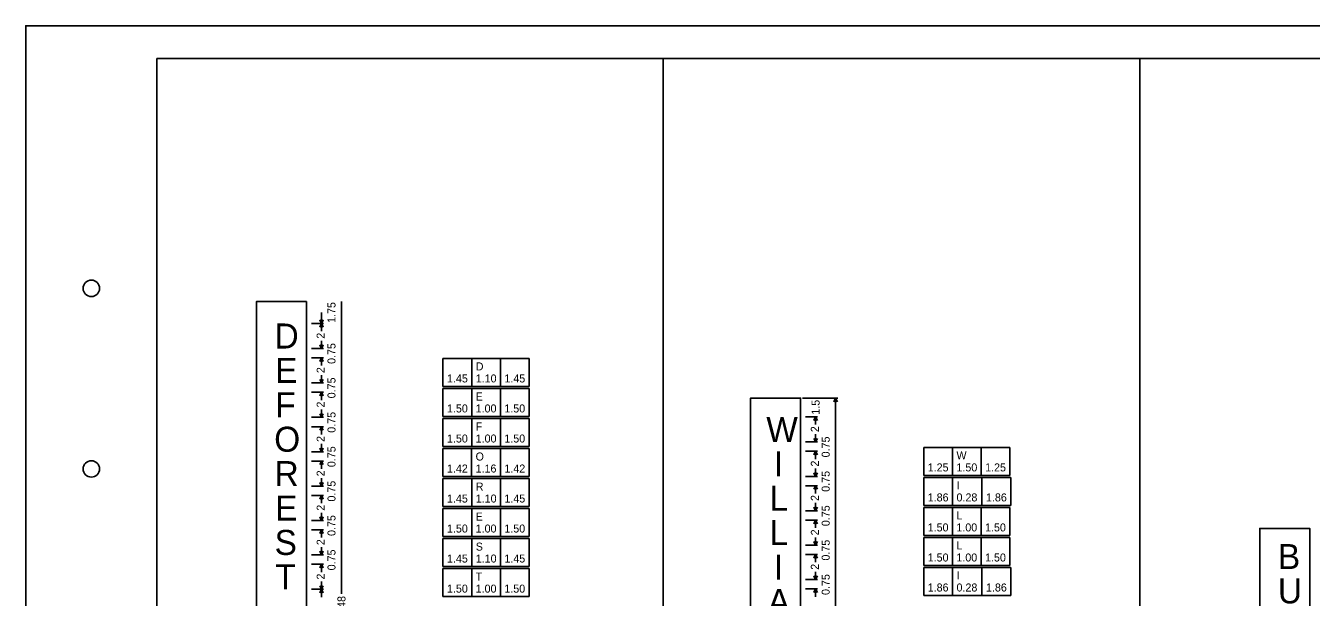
# Model space of a CAD drawing. Extents: x -16.4 to 26.5, y -12.9 to 9.1.
# Drawn here: x -16.37 to 3.22, y 0.39 to 9.09 of the extents above; entities that cross this region are included whole.
import ezdxf

# ---------------------------------------------------------------- set-up
doc = ezdxf.new("R2010")
doc.units = 0
for name, color, linetype in [('SH_Border', 7, 'Continuous'), ('SH_Cut_Line', 7, 'Continuous'), ('SH_Text', 7, 'Continuous')]:
    doc.layers.add(name, color=color, linetype=linetype)

msp = doc.modelspace()

# ---------------------------------------------------------------- linework, layer by layer
at = {"layer": 'SH_Border'}
msp.add_lwpolyline([(-14.371, 8.593), (17.129, 8.593), (17.129, -12.407), (-14.371, -12.407)], close=True, dxfattribs=at)
for centre in [(-15.371, 5.093), (-15.371, 2.343)]:
    msp.add_circle(centre, 0.125, dxfattribs=at)
at = {"layer": 'SH_Cut_Line'}
msp.add_lwpolyline([(-16.371, -12.907), (17.629, -12.907), (17.629, 9.093), (-16.371, 9.093)], close=True, dxfattribs=at)
at = {"layer": 'SH_Text'}
for p, q in [((-6.656, -12.407), (-6.656, 8.593)), ((0.606, -12.407), (0.606, 8.593)), ((-11.865, 4.724), (-11.865, 4.558)), ((-11.56, 0.443), (-11.56, 4.891)), ((-11.834, 4.558), (-12.017, 4.558)), ((-11.892, 4.612), (-11.865, 4.558)), ((-11.892, 4.503), (-11.865, 4.558)), ((-11.838, 4.612), (-11.865, 4.558)), ((-11.865, 4.439), (-11.865, 4.558)), ((-11.838, 4.503), (-11.865, 4.558)), ((-11.834, 4.177), (-12.017, 4.177)), ((-11.892, 4.231), (-11.865, 4.177)), ((-11.865, 4.295), (-11.865, 4.177)), ((-11.838, 4.231), (-11.865, 4.177)), ((-11.834, 4.034), (-12.017, 4.034)), ((-11.892, 3.979), (-11.865, 4.034)), ((-11.865, 3.916), (-11.865, 4.034)), ((-11.838, 3.979), (-11.865, 4.034)), ((-10.013, 4.026), (-10.013, 3.599)), ((-8.7, 4.026), (-10.013, 4.026)), ((-9.575, 4.026), (-9.575, 3.599)), ((-9.138, 4.026), (-9.138, 3.599)), ((-8.7, 4.026), (-8.7, 3.599)), ((-11.865, 3.771), (-11.865, 3.653)), ((-11.834, 3.653), (-12.017, 3.653)), ((-11.892, 3.707), (-11.865, 3.653)), ((-11.838, 3.707), (-11.865, 3.653)), ((-8.7, 3.599), (-10.013, 3.599)), ((-10.013, 3.568), (-10.013, 3.142)), ((-8.701, 3.568), (-10.013, 3.568)), ((-9.576, 3.568), (-9.576, 3.142)), ((-9.138, 3.568), (-9.138, 3.142)), ((-8.701, 3.568), (-8.701, 3.142)), ((-11.834, 3.51), (-12.017, 3.51)), ((-11.892, 3.456), (-11.865, 3.51)), ((-11.865, 3.392), (-11.865, 3.51)), ((-11.838, 3.456), (-11.865, 3.51)), ((-3.999, 3.421), (-4.533, 3.421)), ((-4.304, 3.421), (-4.487, 3.421)), ((-4.057, 3.366), (-4.03, 3.421)), ((-4.03, -0.457), (-4.03, 3.421)), ((-4.002, 3.366), (-4.03, 3.421)), ((-11.892, 3.183), (-11.865, 3.129)), ((-11.865, 3.247), (-11.865, 3.129)), ((-11.838, 3.183), (-11.865, 3.129)), ((-8.701, 3.142), (-10.013, 3.142)), ((-4.304, 3.135), (-4.487, 3.135)), ((-4.362, 3.08), (-4.335, 3.135)), ((-4.335, 3.017), (-4.335, 3.135)), ((-4.307, 3.08), (-4.335, 3.135)), ((-11.834, 3.129), (-12.017, 3.129)), ((-11.834, 2.986), (-12.017, 2.986)), ((-11.892, 2.932), (-11.865, 2.986)), ((-11.865, 2.868), (-11.865, 2.986)), ((-11.838, 2.932), (-11.865, 2.986)), ((-10.013, 3.111), (-10.013, 2.684)), ((-8.701, 3.111), (-10.013, 3.111)), ((-9.576, 3.111), (-9.576, 2.684)), ((-9.138, 3.111), (-9.138, 2.684)), ((-8.701, 3.111), (-8.701, 2.684)), ((-4.304, 2.754), (-4.487, 2.754)), ((-4.362, 2.808), (-4.335, 2.754)), ((-4.335, 2.872), (-4.335, 2.754)), ((-4.307, 2.808), (-4.335, 2.754)), ((-11.834, 2.605), (-12.017, 2.605)), ((-11.892, 2.66), (-11.865, 2.605)), ((-11.865, 2.723), (-11.865, 2.605)), ((-11.838, 2.66), (-11.865, 2.605)), ((-8.701, 2.684), (-10.013, 2.684)), ((-10.013, 2.654), (-10.013, 2.227)), ((-8.702, 2.654), (-10.013, 2.654)), ((-9.577, 2.654), (-9.577, 2.227)), ((-9.138, 2.654), (-9.138, 2.227)), ((-8.702, 2.654), (-8.702, 2.227)), ((-4.304, 2.611), (-4.487, 2.611)), ((-4.362, 2.557), (-4.335, 2.611)), ((-4.335, 2.493), (-4.335, 2.611)), ((-4.307, 2.557), (-4.335, 2.611)), ((-2.688, 2.671), (-2.688, 2.244)), ((-1.375, 2.671), (-2.688, 2.671)), ((-2.25, 2.671), (-2.25, 2.244)), ((-1.813, 2.671), (-1.813, 2.244)), ((-1.375, 2.671), (-1.375, 2.244)), ((-11.834, 2.462), (-12.017, 2.462)), ((-11.892, 2.408), (-11.865, 2.462)), ((-11.865, 2.344), (-11.865, 2.462)), ((-11.838, 2.408), (-11.865, 2.462)), ((-11.865, 2.2), (-11.865, 2.081)), ((-8.702, 2.227), (-10.013, 2.227)), ((-10.013, 2.197), (-10.013, 1.77)), ((-8.7, 2.197), (-10.013, 2.197)), ((-9.575, 2.197), (-9.575, 1.77)), ((-9.138, 2.197), (-9.138, 1.77)), ((-8.7, 2.197), (-8.7, 1.77)), ((-4.304, 2.23), (-4.487, 2.23)), ((-4.362, 2.285), (-4.335, 2.23)), ((-4.335, 2.348), (-4.335, 2.23)), ((-4.307, 2.285), (-4.335, 2.23)), ((-1.375, 2.244), (-2.688, 2.244)), ((-2.688, 2.214), (-2.688, 1.787)), ((-1.36, 2.214), (-2.688, 2.214)), ((-2.249, 2.214), (-2.249, 1.787)), ((-1.8, 2.214), (-1.8, 1.787)), ((-1.36, 2.214), (-1.36, 1.787)), ((-11.834, 2.081), (-12.017, 2.081)), ((-11.892, 2.136), (-11.865, 2.081)), ((-11.838, 2.136), (-11.865, 2.081)), ((-4.304, 2.087), (-4.487, 2.087)), ((-4.362, 2.033), (-4.335, 2.087)), ((-4.335, 1.969), (-4.335, 2.087)), ((-4.307, 2.033), (-4.335, 2.087)), ((-11.834, 1.938), (-12.017, 1.938)), ((-11.892, 1.884), (-11.865, 1.938)), ((-11.865, 1.82), (-11.865, 1.938)), ((-11.838, 1.884), (-11.865, 1.938)), ((-8.7, 1.77), (-10.013, 1.77)), ((-4.335, 1.824), (-4.335, 1.706)), ((-1.36, 1.787), (-2.688, 1.787)), ((-11.892, 1.612), (-11.865, 1.557)), ((-11.865, 1.676), (-11.865, 1.557)), ((-11.838, 1.612), (-11.865, 1.557)), ((-10.013, 1.74), (-10.013, 1.313)), ((-8.701, 1.74), (-10.013, 1.74)), ((-9.576, 1.74), (-9.576, 1.313)), ((-9.138, 1.74), (-9.138, 1.313)), ((-8.701, 1.74), (-8.701, 1.313)), ((-4.304, 1.706), (-4.487, 1.706)), ((-4.362, 1.761), (-4.335, 1.706)), ((-4.307, 1.761), (-4.335, 1.706)), ((-2.688, 1.756), (-2.688, 1.33)), ((-1.376, 1.756), (-2.688, 1.756)), ((-2.251, 1.756), (-2.251, 1.33)), ((-1.814, 1.756), (-1.814, 1.33)), ((-1.376, 1.756), (-1.376, 1.33)), ((-11.834, 1.557), (-12.017, 1.557)), ((-11.834, 1.414), (-12.017, 1.414)), ((-11.892, 1.36), (-11.865, 1.414)), ((-11.865, 1.296), (-11.865, 1.414)), ((-11.838, 1.36), (-11.865, 1.414)), ((-4.304, 1.563), (-4.487, 1.563)), ((-4.362, 1.509), (-4.335, 1.563)), ((-4.335, 1.445), (-4.335, 1.563)), ((-4.307, 1.509), (-4.335, 1.563)), ((-8.701, 1.313), (-10.013, 1.313)), ((-10.013, 1.282), (-10.013, 0.856)), ((-8.7, 1.282), (-10.013, 1.282)), ((-9.575, 1.282), (-9.575, 0.856)), ((-9.138, 1.282), (-9.138, 0.856)), ((-8.7, 1.282), (-8.7, 0.856)), ((-4.304, 1.182), (-4.487, 1.182)), ((-4.362, 1.237), (-4.335, 1.182)), ((-4.335, 1.301), (-4.335, 1.182)), ((-4.307, 1.237), (-4.335, 1.182)), ((-1.376, 1.33), (-2.688, 1.33)), ((-2.688, 1.299), (-2.688, 0.872)), ((-1.376, 1.299), (-2.688, 1.299)), ((-2.251, 1.299), (-2.251, 0.872)), ((-1.814, 1.299), (-1.814, 0.872)), ((-1.376, 1.299), (-1.376, 0.872)), ((-11.834, 1.033), (-12.017, 1.033)), ((-11.892, 1.088), (-11.865, 1.033)), ((-11.865, 1.152), (-11.865, 1.033)), ((-11.838, 1.088), (-11.865, 1.033)), ((-4.304, 1.039), (-4.487, 1.039)), ((-4.362, 0.985), (-4.335, 1.039)), ((-4.335, 0.921), (-4.335, 1.039)), ((-4.307, 0.985), (-4.335, 1.039)), ((-11.834, 0.891), (-12.017, 0.891)), ((-11.892, 0.836), (-11.865, 0.891)), ((-11.865, 0.772), (-11.865, 0.891)), ((-11.838, 0.836), (-11.865, 0.891)), ((-8.7, 0.856), (-10.013, 0.856)), ((-10.013, 0.825), (-10.013, 0.398)), ((-8.701, 0.825), (-10.013, 0.825)), ((-9.576, 0.825), (-9.576, 0.398)), ((-9.138, 0.825), (-9.138, 0.398)), ((-8.701, 0.825), (-8.701, 0.398)), ((-1.376, 0.872), (-2.688, 0.872)), ((-2.688, 0.842), (-2.688, 0.415)), ((-1.36, 0.842), (-2.688, 0.842)), ((-2.249, 0.842), (-2.249, 0.415)), ((-1.8, 0.842), (-1.8, 0.415)), ((-1.36, 0.842), (-1.36, 0.415)), ((-11.865, 0.628), (-11.865, 0.51)), ((-4.304, 0.658), (-4.487, 0.658)), ((-4.362, 0.713), (-4.335, 0.658)), ((-4.335, 0.777), (-4.335, 0.658)), ((-4.307, 0.713), (-4.335, 0.658)), ((-11.834, 0.51), (-12.017, 0.51)), ((-11.892, 0.564), (-11.865, 0.51)), ((-11.892, 0.455), (-11.865, 0.51)), ((-11.838, 0.564), (-11.865, 0.51)), ((-11.865, 0.391), (-11.865, 0.51)), ((-11.838, 0.455), (-11.865, 0.51)), ((-8.701, 0.398), (-10.013, 0.398)), ((-4.304, 0.516), (-4.487, 0.516)), ((-4.362, 0.461), (-4.335, 0.516)), ((-4.335, 0.397), (-4.335, 0.516)), ((-4.307, 0.461), (-4.335, 0.516)), ((-1.36, 0.415), (-2.688, 0.415))]:
    msp.add_line(p, q, dxfattribs=at)
for points in [[(-12.855, -4.253), (-12.093, -4.253), (-12.093, 4.891), (-12.855, 4.891), (-12.855, -4.253), (-12.855, -4.253)], [(-5.325, -4.58), (-4.563, -4.58), (-4.563, 3.421), (-5.325, 3.421), (-5.325, -4.58), (-5.325, -4.58)], [(2.432, -5.42), (3.194, -5.42), (3.194, 1.438), (2.432, 1.438), (2.432, -5.42), (2.432, -5.42)]]:
    msp.add_lwpolyline(points, dxfattribs=at)

# ---------------------------------------------------------------- texts
for s, height, p in [('1.75', 0.1219, (-11.651, 4.567)), ('2', 0.122, (-11.816, 4.326)), ('0.75', 0.1219, (-11.651, 3.942)), ('2', 0.122, (-11.816, 3.802)), ('0.75', 0.1219, (-11.651, 3.418)), ('2', 0.122, (-11.816, 3.278)), ('1.5', 0.1219, (-4.274, 3.169)), ('0.75', 0.1219, (-11.651, 2.894)), ('2', 0.122, (-4.286, 2.903)), ('2', 0.122, (-11.816, 2.754)), ('0.75', 0.1219, (-4.121, 2.519)), ('0.75', 0.1219, (-11.651, 2.37)), ('2', 0.122, (-4.286, 2.379)), ('2', 0.122, (-11.816, 2.23)), ('0.75', 0.1219, (-11.651, 1.846)), ('0.75', 0.1219, (-4.121, 1.995)), ('2', 0.122, (-11.816, 1.706)), ('2', 0.122, (-4.286, 1.855)), ('0.75', 0.1219, (-4.121, 1.471)), ('0.75', 0.1219, (-11.651, 1.322)), ('2', 0.122, (-4.286, 1.331)), ('2', 0.122, (-11.816, 1.182)), ('0.75', 0.1219, (-4.121, 0.947)), ('0.75', 0.1219, (-11.651, 0.798)), ('2', 0.122, (-4.286, 0.807)), ('2', 0.122, (-11.816, 0.658)), ('0.75', 0.1219, (-4.121, 0.423)), ('48', 0.1219, (-11.499, 0.226))]:
    msp.add_text(s, height=height, rotation=90.0002, dxfattribs=at).set_placement(p)
for s, height, p in [('D', 0.381, (-12.579, 4.177)), ('E', 0.381, (-12.57, 3.653)), ('D', 0.122, (-9.514, 3.843)), ('1.45', 0.1219, (-9.952, 3.66)), ('1.10', 0.1219, (-9.514, 3.66)), ('1.45', 0.1219, (-9.077, 3.66)), ('F', 0.381, (-12.57, 3.129)), ('E', 0.122, (-9.515, 3.385)), ('1.50', 0.1219, (-9.952, 3.203)), ('1.00', 0.1219, (-9.515, 3.203)), ('1.50', 0.1219, (-9.078, 3.203)), ('W', 0.381, (-5.087, 2.754)), ('O', 0.381, (-12.585, 2.605)), ('F', 0.122, (-9.515, 2.928)), ('1.50', 0.1219, (-9.952, 2.745)), ('1.00', 0.1219, (-9.515, 2.745)), ('1.50', 0.1219, (-9.078, 2.745)), ('O', 0.122, (-9.516, 2.471)), ('I', 0.381, (-4.971, 2.23)), ('W', 0.122, (-2.189, 2.488)), ('R', 0.381, (-12.579, 2.081)), ('1.42', 0.1219, (-9.952, 2.288)), ('1.16', 0.1219, (-9.516, 2.288)), ('1.42', 0.1219, (-9.077, 2.288)), ('1.25', 0.1219, (-2.627, 2.305)), ('1.50', 0.1219, (-2.189, 2.305)), ('1.25', 0.1219, (-1.752, 2.305)), ('R', 0.122, (-9.514, 2.014)), ('L', 0.381, (-5.039, 1.706)), ('1.86', 0.1219, (-2.627, 1.848)), ('0.28', 0.1219, (-2.188, 1.848)), ('I', 0.122, (-2.188, 2.031)), ('1.86', 0.1219, (-1.739, 1.848)), ('E', 0.381, (-12.57, 1.557)), ('1.45', 0.1219, (-9.952, 1.831)), ('1.10', 0.1219, (-9.514, 1.831)), ('1.45', 0.1219, (-9.077, 1.831)), ('E', 0.122, (-9.515, 1.557)), ('L', 0.122, (-2.19, 1.574)), ('S', 0.381, (-12.579, 1.033)), ('1.50', 0.1219, (-9.952, 1.374)), ('1.00', 0.1219, (-9.515, 1.374)), ('1.50', 0.1219, (-9.078, 1.374)), ('L', 0.381, (-5.039, 1.182)), ('1.50', 0.1219, (-2.627, 1.391)), ('1.00', 0.1219, (-2.19, 1.391)), ('1.50', 0.1219, (-1.753, 1.391)), ('S', 0.122, (-9.514, 1.099)), ('L', 0.122, (-2.19, 1.116)), ('B', 0.381, (2.709, 0.818)), ('1.45', 0.1219, (-9.952, 0.917)), ('1.10', 0.1219, (-9.514, 0.917)), ('1.45', 0.1219, (-9.077, 0.917)), ('I', 0.381, (-4.971, 0.658)), ('1.50', 0.1219, (-2.627, 0.933)), ('1.00', 0.1219, (-2.19, 0.933)), ('1.50', 0.1219, (-1.753, 0.933)), ('T', 0.381, (-12.57, 0.51)), ('T', 0.122, (-9.515, 0.642)), ('1.86', 0.1219, (-2.627, 0.476)), ('0.28', 0.1219, (-2.188, 0.476)), ('I', 0.122, (-2.188, 0.659)), ('1.86', 0.1219, (-1.739, 0.476)), ('U', 0.381, (2.709, 0.295)), ('1.50', 0.1219, (-9.952, 0.459)), ('1.00', 0.1219, (-9.515, 0.459)), ('1.50', 0.1219, (-9.078, 0.459)), ('A', 0.381, (-5.063, 0.135))]:
    msp.add_text(s, height=height, dxfattribs=at).set_placement(p)

doc.saveas('drawing.dxf')
